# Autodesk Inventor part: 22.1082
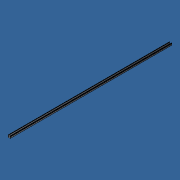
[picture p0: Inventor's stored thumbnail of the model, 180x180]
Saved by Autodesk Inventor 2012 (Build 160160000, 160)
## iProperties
Created: 2007-05
Part Number: 22.1082
Material: PVC-U
Document SubType Name: Modeling
Designer: Andy Moles
Density: 1.4 g/cm^3
Description: CONDUIT 32 BOTTOM
Stock Number: 22.1082 CONDUIT 32 BOTTOM
Author: Andy Moles
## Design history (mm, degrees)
sketch "Sketch1"
  geometry: L1 (-12, 2)-(0, 2); L2 (-13, 17.83)-(-13, 3); L3 (-10.902, 22)-(-12.732, 18.83); L4 (-13.725, 25.226)-(-13.416, 25.76); L5 (-14.464, 18.83)-(-12.201, 22.75); L6 (-15, 3)-(-15, 16.83); L7 (0, 0)-(-12, 0); L8 (13, 17.83)-(13, 3); L9 (15, 3)-(15, 16.83); L10 (12, 2)-(0, 2); L11 (0, 0)-(12, 0); L12 (10.902, 22)-(12.732, 18.83); L13 (14.464, 18.83)-(12.201, 22.75); L14 (13.725, 25.226)-(13.416, 25.76); A1 r 1 centre (-12, 3) between (-13, 3) and (-12, 2); A2 r 2 centre (-11, 17.83) between (-12.732, 18.83) and (-13, 17.83); A3 r 3 centre (-13.5, 23.5) between (-10.902, 22) and (-12.075, 26.14); A4 r 1 centre (-12.55, 25.26) between (-12.075, 26.14) and (-13.416, 25.76); A5 r 0.5 centre (-13.3, 25.49) between (-13.725, 25.226) and (-13.35, 24.992); A6 r 1.5 centre (-13.5, 23.5) between (-12.201, 22.75) and (-13.35, 24.992); A7 r 4 centre (-11, 16.83) between (-14.464, 18.83) and (-15, 16.83); A8 r 3 centre (-12, 3) between (-15, 3) and (-12, 0); A9 r 1 centre (12, 3) between (12, 2) and (13, 3); A10 r 3 centre (12, 3) between (12, 0) and (15, 3); A11 r 4 centre (11, 16.83) between (15, 16.83) and (14.464, 18.83); A12 r 2 centre (11, 17.83) between (13, 17.83) and (12.732, 18.83); A13 r 1.5 centre (13.5, 23.5) between (13.35, 24.992) and (12.201, 22.75); A14 r 3 centre (13.5, 23.5) between (12.075, 26.14) and (10.902, 22); A15 r 0.5 centre (13.3, 25.49) between (13.35, 24.992) and (13.725, 25.226); A16 r 1 centre (12.55, 25.26) between (13.416, 25.76) and (12.075, 26.14); 3 further points
  constraints: 32 point on circle, 28 end point, 16 centre point, 2 tangent, 2 vertical alignment, 1 parallel, 1 vertical
  dimensions: "d34" = 13.83015 distance of L6.start L6.end; "d35" = 14.83013 distance of L2.start L2.end; "d37" = 1 distance from line of L1.start L2; "d39" = 2 distance between parallel lines of L6 L2
extrude "Extrusion2" new body sketch "Sketch1" distance "d2" = 2000; taper "d3" = 0 deg
sketch "Sketch2"
  geometry: L1 (24, 2000)-(0, 2000) reference; L2 (8.5, 1942.25)-(9.655, 1942.25); L3 (8.5, 1937.75)-(9.655, 1937.75); L4 (15.5, 1937.75)-(14.345, 1937.75); L5 (15.5, 1942.25)-(14.345, 1942.25); L6 (14.25, 1811.5)-(14.25, 1812.655); L7 (9.75, 1818.5)-(9.75, 1817.345); L8 (14.25, 1818.5)-(14.25, 1817.345); L9 (9.75, 1811.5)-(9.75, 1812.655); L10 (-3, 0)-(-3, 2000) reference; C1 r 1.35 at (12, 1915); C2 r 1.35 at (12, 1790); A1 r 2.25 centre (15.5, 1940) between (15.5, 1937.75) and (15.5, 1942.25); A2 r 2.25 centre (8.5, 1940) between (8.5, 1942.25) and (8.5, 1937.75); A3 r 3.25 centre (12, 1940) between (14.345, 1942.25) and (9.655, 1942.25); A4 r 3.25 centre (12, 1940) between (9.655, 1937.75) and (14.345, 1937.75); A5 r 2.25 centre (12, 1811.5) between (9.75, 1811.5) and (14.25, 1811.5); A6 r 3.25 centre (12, 1815) between (9.75, 1817.345) and (9.75, 1812.655); A7 r 3.25 centre (12, 1815) between (14.25, 1812.655) and (14.25, 1817.345); A8 r 2.25 centre (12, 1818.5) between (14.25, 1818.5) and (9.75, 1818.5); 3 further points
  constraints: 16 end point, 16 point on circle, 10 centre point, 8 tangent, 7 vertical alignment, 6 equal length, 3 equal radius, 2 horizontal alignment, 2 midpoint, 1 horizontal, 1 parallel
  dimensions: "d13" = 2.7 diameter of C1; "d14" = 60 distance from line of A3.centre L1; "d15" = 85 distance from line of C1.centre L1; "d16" = 4.5 diameter of A2; "d17" = 3.5 distance of A3.centre A2.centre; "d18" = 3.5 distance of A3.centre A1.centre (= d17); "d19" = 3.25 radius of A4; "d20" = 3.25 radius of A3; "d21" = 4.5 diameter of A5; "d22" = 3.5 distance of A6.centre A5.centre; "d23" = 3.5 distance of A6.centre A8.centre (= d22); "d24" = 3.25 radius of A7; "d25" = 3.25 radius of A6; "d26" = 125 distance of A6.centre A3.centre; "d27" = 25 distance of A6.centre C2.centre
extrude "Extrusion3" cut sketch "Sketch2" distance "d28" = 2000; taper "d29" = 0 deg
pattern_linear "Rectangular Pattern1" dims "d32" = 250
body "Solid2"
other parameters: "d4" = 6.5, "d12" = 6.5
